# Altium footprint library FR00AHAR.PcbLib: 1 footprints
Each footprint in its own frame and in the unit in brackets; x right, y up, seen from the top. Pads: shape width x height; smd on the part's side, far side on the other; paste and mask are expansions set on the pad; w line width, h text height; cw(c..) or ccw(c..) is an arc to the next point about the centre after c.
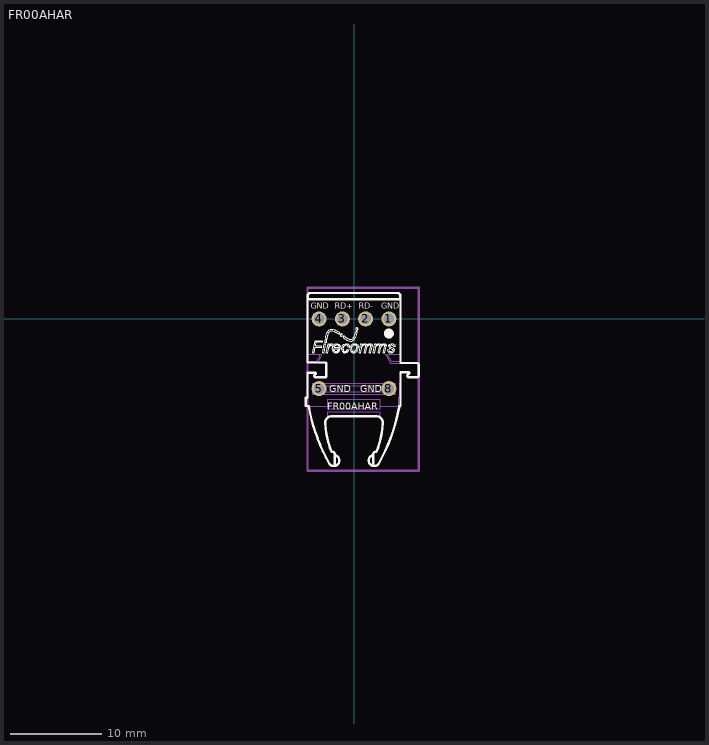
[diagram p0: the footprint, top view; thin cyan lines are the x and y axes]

## FR00AHAR [mil] "RedLink® Analogue Receiver Horizontal Package"
height 300
pads (6):
  round 65 hole 45: 1(150,0) 2(50,0) 3(-50,0) 4(-150,0) 5(-150,-300) 8(150,-300)
Top Overlay:
  drawing of 1776 lines, arcs and shapes, not listed
  text "GND" at -106.3,-314.96 h30
  text "GND" at 27.56,-314.96 h30
  text "GND" at -185.04,43.31 h25
  text "RD+" at -82.68,43.31 h25
  text "RD-" at 19.68,43.31 h25
  text "GND" at 118.11,43.31 h25
  text "FR00AHAR" at -115,-390 h30
Mechanical 2:
  lines w10: 278.74,-653.54 278.74,133.26 278.14,133.86 -200,133.86 -200,-653.54 279,-653.54
Mechanical 19:
  drawing of 1055 lines, arcs and shapes, not listed
3D body "Horizontal RedLink Connector.stp": height 301.22, standoff -144.78, extent -207.87,-627.68 278.75,116.41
